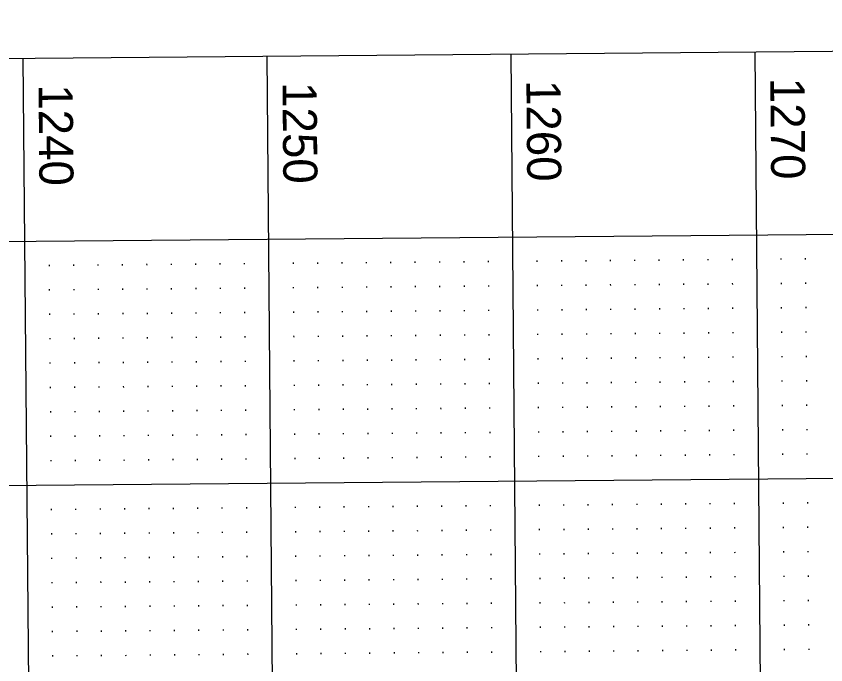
# Model space of a CAD drawing. Extents: x 2149873 to 2152007, y 140538 to 142349.
# Drawn here: x 2150024.4 to 2150190.3, y 142035.8 to 142168.7 of the extents above; entities that cross this region are included whole.
import ezdxf

# ---------------------------------------------------------------- set-up
doc = ezdxf.new("R2010")
doc.units = 0
for name, color, linetype in [('SHT_Plan_Profile_Sheet_Elev_Txt', 7, 'Continuous'), ('SHT_Profile_Grid_Major', 7, 'Continuous'), ('SHT_Profile_Grid_Minor', 7, 'Continuous'), ('SHT_Sheet_Border', 7, 'Continuous')]:
    doc.layers.add(name, color=color, linetype=linetype)

msp = doc.modelspace()

# ---------------------------------------------------------------- linework, layer by layer
at = {"layer": 'SHT_Profile_Grid_Major'}
for p, q in [((2150025.72, 142160.07), (2150039.51, 140585.13)), ((2150075.72, 142160.51), (2150089.51, 140585.57)), ((2150125.72, 142160.94), (2150139.51, 140586)), ((2150175.72, 142161.38), (2150189.5, 140586.44)), ((2149976.49, 142072.13), (2150476.47, 142076.51))]:
    msp.add_line(p, q, dxfattribs=at)
at = {"layer": 'SHT_Profile_Grid_Minor'}
for p, q in [((2150116.09, 142118.48), (2150116.09, 142118.23)), ((2150121.09, 142118.53), (2150121.09, 142118.28)), ((2150131.09, 142118.61), (2150131.09, 142118.36)), ((2150136.09, 142118.66), (2150136.09, 142118.41)), ((2150141.09, 142118.7), (2150141.09, 142118.45)), ((2150146.09, 142118.75), (2150146.09, 142118.5)), ((2150151.09, 142118.79), (2150151.09, 142118.54)), ((2150156.09, 142118.83), (2150156.09, 142118.58)), ((2150161.09, 142118.88), (2150161.09, 142118.63)), ((2150166.09, 142118.92), (2150166.09, 142118.67)), ((2150171.09, 142118.96), (2150171.09, 142118.71)), ((2150181.09, 142119.05), (2150181.09, 142118.8)), ((2150186.09, 142119.1), (2150186.09, 142118.85)), ((2150031.09, 142117.74), (2150031.1, 142117.49)), ((2150036.09, 142117.78), (2150036.1, 142117.53)), ((2150041.09, 142117.83), (2150041.1, 142117.58)), ((2150046.09, 142117.87), (2150046.1, 142117.62)), ((2150051.09, 142117.91), (2150051.1, 142117.66)), ((2150056.09, 142117.96), (2150056.1, 142117.71)), ((2150061.09, 142118), (2150061.1, 142117.75)), ((2150066.09, 142118.05), (2150066.1, 142117.8)), ((2150071.09, 142118.09), (2150071.1, 142117.84)), ((2150081.09, 142118.18), (2150081.1, 142117.93)), ((2150086.09, 142118.22), (2150086.09, 142117.97)), ((2150091.09, 142118.26), (2150091.09, 142118.01)), ((2150096.09, 142118.31), (2150096.09, 142118.06)), ((2150101.09, 142118.35), (2150101.09, 142118.1)), ((2150106.09, 142118.4), (2150106.09, 142118.15)), ((2150111.09, 142118.44), (2150111.09, 142118.19)), ((2150116.14, 142113.48), (2150116.14, 142113.23)), ((2150121.14, 142113.53), (2150121.14, 142113.28)), ((2150131.13, 142113.61), (2150131.14, 142113.36)), ((2150136.13, 142113.66), (2150136.14, 142113.41)), ((2150141.13, 142113.7), (2150141.14, 142113.45)), ((2150146.13, 142113.75), (2150146.14, 142113.5)), ((2150151.13, 142113.79), (2150151.14, 142113.54)), ((2150156.13, 142113.83), (2150156.14, 142113.58)), ((2150161.13, 142113.88), (2150161.14, 142113.63)), ((2150166.13, 142113.92), (2150166.14, 142113.67)), ((2150171.13, 142113.96), (2150171.14, 142113.71)), ((2150181.13, 142114.05), (2150181.14, 142113.8)), ((2150186.13, 142114.1), (2150186.13, 142113.85)), ((2150031.14, 142112.74), (2150031.14, 142112.49)), ((2150036.14, 142112.78), (2150036.14, 142112.53)), ((2150041.14, 142112.83), (2150041.14, 142112.58)), ((2150046.14, 142112.87), (2150046.14, 142112.62)), ((2150051.14, 142112.91), (2150051.14, 142112.66)), ((2150056.14, 142112.96), (2150056.14, 142112.71)), ((2150061.14, 142113), (2150061.14, 142112.75)), ((2150066.14, 142113.05), (2150066.14, 142112.8)), ((2150071.14, 142113.09), (2150071.14, 142112.84)), ((2150081.14, 142113.18), (2150081.14, 142112.93)), ((2150086.14, 142113.22), (2150086.14, 142112.97)), ((2150091.14, 142113.26), (2150091.14, 142113.01)), ((2150096.14, 142113.31), (2150096.14, 142113.06)), ((2150101.14, 142113.35), (2150101.14, 142113.1)), ((2150106.14, 142113.4), (2150106.14, 142113.15)), ((2150111.14, 142113.44), (2150111.14, 142113.19)), ((2150121.18, 142108.53), (2150121.18, 142108.28)), ((2150131.18, 142108.61), (2150131.18, 142108.36)), ((2150136.18, 142108.66), (2150136.18, 142108.41)), ((2150141.18, 142108.7), (2150141.18, 142108.45)), ((2150146.18, 142108.75), (2150146.18, 142108.5)), ((2150151.18, 142108.79), (2150151.18, 142108.54)), ((2150156.18, 142108.83), (2150156.18, 142108.58)), ((2150161.18, 142108.88), (2150161.18, 142108.63)), ((2150166.18, 142108.92), (2150166.18, 142108.67)), ((2150171.18, 142108.96), (2150171.18, 142108.71)), ((2150181.18, 142109.05), (2150181.18, 142108.8)), ((2150186.18, 142109.1), (2150186.18, 142108.85)), ((2150031.18, 142107.74), (2150031.18, 142107.49)), ((2150036.18, 142107.78), (2150036.18, 142107.53)), ((2150041.18, 142107.83), (2150041.18, 142107.58)), ((2150046.18, 142107.87), (2150046.18, 142107.62)), ((2150051.18, 142107.91), (2150051.18, 142107.66)), ((2150056.18, 142107.96), (2150056.18, 142107.71)), ((2150061.18, 142108), (2150061.18, 142107.75)), ((2150066.18, 142108.05), (2150066.18, 142107.8)), ((2150071.18, 142108.09), (2150071.18, 142107.84)), ((2150081.18, 142108.18), (2150081.18, 142107.93)), ((2150086.18, 142108.22), (2150086.18, 142107.97)), ((2150091.18, 142108.26), (2150091.18, 142108.01)), ((2150096.18, 142108.31), (2150096.18, 142108.06)), ((2150101.18, 142108.35), (2150101.18, 142108.1)), ((2150106.18, 142108.4), (2150106.18, 142108.15)), ((2150111.18, 142108.44), (2150111.18, 142108.19)), ((2150116.18, 142108.48), (2150116.18, 142108.23)), ((2150121.22, 142103.53), (2150121.22, 142103.28)), ((2150131.22, 142103.62), (2150131.22, 142103.37)), ((2150136.22, 142103.66), (2150136.22, 142103.41)), ((2150141.22, 142103.7), (2150141.22, 142103.45)), ((2150146.22, 142103.75), (2150146.22, 142103.5)), ((2150151.22, 142103.79), (2150151.22, 142103.54)), ((2150156.22, 142103.83), (2150156.22, 142103.58)), ((2150161.22, 142103.88), (2150161.22, 142103.63)), ((2150166.22, 142103.92), (2150166.22, 142103.67)), ((2150171.22, 142103.97), (2150171.22, 142103.72)), ((2150181.22, 142104.05), (2150181.22, 142103.8)), ((2150186.22, 142104.1), (2150186.22, 142103.85)), ((2150031.23, 142102.74), (2150031.23, 142102.49)), ((2150036.23, 142102.78), (2150036.23, 142102.53)), ((2150041.23, 142102.83), (2150041.23, 142102.58)), ((2150046.23, 142102.87), (2150046.23, 142102.62)), ((2150051.23, 142102.91), (2150051.23, 142102.66)), ((2150056.23, 142102.96), (2150056.23, 142102.71)), ((2150061.22, 142103), (2150061.23, 142102.75)), ((2150066.22, 142103.05), (2150066.23, 142102.8)), ((2150071.22, 142103.09), (2150071.23, 142102.84)), ((2150081.22, 142103.18), (2150081.23, 142102.93)), ((2150086.22, 142103.22), (2150086.23, 142102.97)), ((2150091.22, 142103.26), (2150091.23, 142103.01)), ((2150096.22, 142103.31), (2150096.23, 142103.06)), ((2150101.22, 142103.35), (2150101.23, 142103.1)), ((2150106.22, 142103.4), (2150106.23, 142103.15)), ((2150111.22, 142103.44), (2150111.23, 142103.19)), ((2150116.22, 142103.48), (2150116.22, 142103.23)), ((2150131.27, 142098.62), (2150131.27, 142098.37)), ((2150136.27, 142098.66), (2150136.27, 142098.41)), ((2150141.27, 142098.7), (2150141.27, 142098.45)), ((2150146.27, 142098.75), (2150146.27, 142098.5)), ((2150151.27, 142098.79), (2150151.27, 142098.54)), ((2150156.27, 142098.83), (2150156.27, 142098.58)), ((2150161.26, 142098.88), (2150161.27, 142098.63)), ((2150166.26, 142098.92), (2150166.27, 142098.67)), ((2150171.26, 142098.97), (2150171.27, 142098.72)), ((2150181.26, 142099.05), (2150181.27, 142098.8)), ((2150186.26, 142099.1), (2150186.27, 142098.85)), ((2150031.27, 142097.74), (2150031.27, 142097.49)), ((2150036.27, 142097.78), (2150036.27, 142097.53)), ((2150041.27, 142097.83), (2150041.27, 142097.58)), ((2150046.27, 142097.87), (2150046.27, 142097.62)), ((2150051.27, 142097.92), (2150051.27, 142097.67)), ((2150056.27, 142097.96), (2150056.27, 142097.71)), ((2150061.27, 142098), (2150061.27, 142097.75)), ((2150066.27, 142098.05), (2150066.27, 142097.8)), ((2150071.27, 142098.09), (2150071.27, 142097.84)), ((2150081.27, 142098.18), (2150081.27, 142097.93)), ((2150086.27, 142098.22), (2150086.27, 142097.97)), ((2150091.27, 142098.27), (2150091.27, 142098.02)), ((2150096.27, 142098.31), (2150096.27, 142098.06)), ((2150101.27, 142098.35), (2150101.27, 142098.1)), ((2150106.27, 142098.4), (2150106.27, 142098.15)), ((2150111.27, 142098.44), (2150111.27, 142098.19)), ((2150116.27, 142098.48), (2150116.27, 142098.23)), ((2150121.27, 142098.53), (2150121.27, 142098.28)), ((2150131.31, 142093.62), (2150131.31, 142093.37)), ((2150136.31, 142093.66), (2150136.31, 142093.41)), ((2150141.31, 142093.7), (2150141.31, 142093.45)), ((2150146.31, 142093.75), (2150146.31, 142093.5)), ((2150151.31, 142093.79), (2150151.31, 142093.54)), ((2150156.31, 142093.83), (2150156.31, 142093.58)), ((2150161.31, 142093.88), (2150161.31, 142093.63)), ((2150166.31, 142093.92), (2150166.31, 142093.67)), ((2150171.31, 142093.97), (2150171.31, 142093.72)), ((2150181.31, 142094.05), (2150181.31, 142093.8)), ((2150186.31, 142094.1), (2150186.31, 142093.85)), ((2150031.31, 142092.74), (2150031.32, 142092.49)), ((2150036.31, 142092.78), (2150036.32, 142092.53)), ((2150041.31, 142092.83), (2150041.32, 142092.58)), ((2150046.31, 142092.87), (2150046.32, 142092.62)), ((2150051.31, 142092.92), (2150051.32, 142092.67)), ((2150056.31, 142092.96), (2150056.31, 142092.71)), ((2150061.31, 142093), (2150061.31, 142092.75)), ((2150066.31, 142093.05), (2150066.31, 142092.8)), ((2150071.31, 142093.09), (2150071.31, 142092.84)), ((2150081.31, 142093.18), (2150081.31, 142092.93)), ((2150086.31, 142093.22), (2150086.31, 142092.97)), ((2150091.31, 142093.27), (2150091.31, 142093.02)), ((2150096.31, 142093.31), (2150096.31, 142093.06)), ((2150101.31, 142093.35), (2150101.31, 142093.1)), ((2150106.31, 142093.4), (2150106.31, 142093.15)), ((2150111.31, 142093.44), (2150111.31, 142093.19)), ((2150116.31, 142093.48), (2150116.31, 142093.23)), ((2150121.31, 142093.53), (2150121.31, 142093.28)), ((2150131.35, 142088.62), (2150131.36, 142088.37)), ((2150136.35, 142088.66), (2150136.36, 142088.41)), ((2150141.35, 142088.7), (2150141.36, 142088.45)), ((2150146.35, 142088.75), (2150146.36, 142088.5)), ((2150151.35, 142088.79), (2150151.35, 142088.54)), ((2150156.35, 142088.83), (2150156.35, 142088.58)), ((2150161.35, 142088.88), (2150161.35, 142088.63)), ((2150166.35, 142088.92), (2150166.35, 142088.67)), ((2150171.35, 142088.97), (2150171.35, 142088.72)), ((2150181.35, 142089.05), (2150181.35, 142088.8)), ((2150186.35, 142089.1), (2150186.35, 142088.85)), ((2150031.36, 142087.74), (2150031.36, 142087.49)), ((2150036.36, 142087.78), (2150036.36, 142087.53)), ((2150041.36, 142087.83), (2150041.36, 142087.58)), ((2150046.36, 142087.87), (2150046.36, 142087.62)), ((2150051.36, 142087.92), (2150051.36, 142087.67)), ((2150056.36, 142087.96), (2150056.36, 142087.71)), ((2150061.36, 142088), (2150061.36, 142087.75)), ((2150066.36, 142088.05), (2150066.36, 142087.8)), ((2150071.36, 142088.09), (2150071.36, 142087.84)), ((2150081.36, 142088.18), (2150081.36, 142087.93)), ((2150086.36, 142088.22), (2150086.36, 142087.97)), ((2150091.36, 142088.27), (2150091.36, 142088.02)), ((2150096.35, 142088.31), (2150096.36, 142088.06)), ((2150101.35, 142088.35), (2150101.36, 142088.1)), ((2150106.35, 142088.4), (2150106.36, 142088.15)), ((2150111.35, 142088.44), (2150111.36, 142088.19)), ((2150116.35, 142088.48), (2150116.36, 142088.23)), ((2150121.35, 142088.53), (2150121.36, 142088.28)), ((2150131.4, 142083.62), (2150131.4, 142083.37)), ((2150136.4, 142083.66), (2150136.4, 142083.41)), ((2150141.4, 142083.7), (2150141.4, 142083.45)), ((2150146.4, 142083.75), (2150146.4, 142083.5)), ((2150151.4, 142083.79), (2150151.4, 142083.54)), ((2150156.4, 142083.83), (2150156.4, 142083.58)), ((2150161.4, 142083.88), (2150161.4, 142083.63)), ((2150166.4, 142083.92), (2150166.4, 142083.67)), ((2150171.4, 142083.97), (2150171.4, 142083.72)), ((2150181.4, 142084.05), (2150181.4, 142083.8)), ((2150186.4, 142084.1), (2150186.4, 142083.85)), ((2150031.4, 142082.74), (2150031.4, 142082.49)), ((2150036.4, 142082.78), (2150036.4, 142082.53)), ((2150041.4, 142082.83), (2150041.4, 142082.58)), ((2150046.4, 142082.87), (2150046.4, 142082.62)), ((2150051.4, 142082.92), (2150051.4, 142082.67)), ((2150056.4, 142082.96), (2150056.4, 142082.71)), ((2150061.4, 142083), (2150061.4, 142082.75)), ((2150066.4, 142083.05), (2150066.4, 142082.8)), ((2150071.4, 142083.09), (2150071.4, 142082.84)), ((2150081.4, 142083.18), (2150081.4, 142082.93)), ((2150086.4, 142083.22), (2150086.4, 142082.97)), ((2150091.4, 142083.27), (2150091.4, 142083.02)), ((2150096.4, 142083.31), (2150096.4, 142083.06)), ((2150101.4, 142083.35), (2150101.4, 142083.1)), ((2150106.4, 142083.4), (2150106.4, 142083.15)), ((2150111.4, 142083.44), (2150111.4, 142083.19)), ((2150116.4, 142083.48), (2150116.4, 142083.23)), ((2150121.4, 142083.53), (2150121.4, 142083.28)), ((2150136.44, 142078.66), (2150136.44, 142078.41)), ((2150141.44, 142078.7), (2150141.44, 142078.45)), ((2150146.44, 142078.75), (2150146.44, 142078.5)), ((2150151.44, 142078.79), (2150151.44, 142078.54)), ((2150156.44, 142078.83), (2150156.44, 142078.58)), ((2150161.44, 142078.88), (2150161.44, 142078.63)), ((2150166.44, 142078.92), (2150166.44, 142078.67)), ((2150171.44, 142078.97), (2150171.44, 142078.72)), ((2150181.44, 142079.05), (2150181.44, 142078.8)), ((2150186.44, 142079.1), (2150186.44, 142078.85)), ((2150031.44, 142077.74), (2150031.45, 142077.49)), ((2150036.44, 142077.78), (2150036.45, 142077.53)), ((2150041.44, 142077.83), (2150041.45, 142077.58)), ((2150046.44, 142077.87), (2150046.45, 142077.62)), ((2150051.44, 142077.92), (2150051.45, 142077.67)), ((2150056.44, 142077.96), (2150056.45, 142077.71)), ((2150061.44, 142078), (2150061.45, 142077.75)), ((2150066.44, 142078.05), (2150066.45, 142077.8)), ((2150071.44, 142078.09), (2150071.45, 142077.84)), ((2150081.44, 142078.18), (2150081.45, 142077.93)), ((2150086.44, 142078.22), (2150086.44, 142077.97)), ((2150091.44, 142078.27), (2150091.44, 142078.02)), ((2150096.44, 142078.31), (2150096.44, 142078.06)), ((2150101.44, 142078.35), (2150101.44, 142078.1)), ((2150106.44, 142078.4), (2150106.44, 142078.15)), ((2150111.44, 142078.44), (2150111.44, 142078.19)), ((2150116.44, 142078.48), (2150116.44, 142078.23)), ((2150121.44, 142078.53), (2150121.44, 142078.28)), ((2150131.44, 142078.62), (2150131.44, 142078.37)), ((2150141.53, 142068.7), (2150141.53, 142068.45)), ((2150146.53, 142068.75), (2150146.53, 142068.5)), ((2150151.53, 142068.79), (2150151.53, 142068.54)), ((2150156.53, 142068.84), (2150156.53, 142068.59)), ((2150161.53, 142068.88), (2150161.53, 142068.63)), ((2150166.53, 142068.92), (2150166.53, 142068.67)), ((2150171.53, 142068.97), (2150171.53, 142068.72)), ((2150181.53, 142069.05), (2150181.53, 142068.8)), ((2150186.53, 142069.1), (2150186.53, 142068.85)), ((2150031.53, 142067.74), (2150031.53, 142067.49)), ((2150036.53, 142067.78), (2150036.53, 142067.53)), ((2150041.53, 142067.83), (2150041.53, 142067.58)), ((2150046.53, 142067.87), (2150046.53, 142067.62)), ((2150051.53, 142067.92), (2150051.53, 142067.67)), ((2150056.53, 142067.96), (2150056.53, 142067.71)), ((2150061.53, 142068), (2150061.53, 142067.75)), ((2150066.53, 142068.05), (2150066.53, 142067.8)), ((2150071.53, 142068.09), (2150071.53, 142067.84)), ((2150081.53, 142068.18), (2150081.53, 142067.93)), ((2150086.53, 142068.22), (2150086.53, 142067.97)), ((2150091.53, 142068.27), (2150091.53, 142068.02)), ((2150096.53, 142068.31), (2150096.53, 142068.06)), ((2150101.53, 142068.35), (2150101.53, 142068.1)), ((2150106.53, 142068.4), (2150106.53, 142068.15)), ((2150111.53, 142068.44), (2150111.53, 142068.19)), ((2150116.53, 142068.49), (2150116.53, 142068.24)), ((2150121.53, 142068.53), (2150121.53, 142068.28)), ((2150131.53, 142068.62), (2150131.53, 142068.37)), ((2150136.53, 142068.66), (2150136.53, 142068.41)), ((2150141.57, 142063.7), (2150141.57, 142063.45)), ((2150146.57, 142063.75), (2150146.57, 142063.5)), ((2150151.57, 142063.79), (2150151.57, 142063.54)), ((2150156.57, 142063.84), (2150156.57, 142063.59)), ((2150161.57, 142063.88), (2150161.57, 142063.63)), ((2150166.57, 142063.92), (2150166.57, 142063.67)), ((2150171.57, 142063.97), (2150171.57, 142063.72)), ((2150181.57, 142064.05), (2150181.57, 142063.8)), ((2150186.57, 142064.1), (2150186.57, 142063.85)), ((2150031.58, 142062.74), (2150031.58, 142062.49)), ((2150036.58, 142062.79), (2150036.58, 142062.54)), ((2150041.58, 142062.83), (2150041.58, 142062.58)), ((2150046.58, 142062.87), (2150046.58, 142062.62)), ((2150051.58, 142062.92), (2150051.58, 142062.67)), ((2150056.58, 142062.96), (2150056.58, 142062.71)), ((2150061.58, 142063), (2150061.58, 142062.75)), ((2150066.57, 142063.05), (2150066.58, 142062.8)), ((2150071.57, 142063.09), (2150071.58, 142062.84)), ((2150081.57, 142063.18), (2150081.58, 142062.93)), ((2150086.57, 142063.22), (2150086.58, 142062.97)), ((2150091.57, 142063.27), (2150091.58, 142063.02)), ((2150096.57, 142063.31), (2150096.58, 142063.06)), ((2150101.57, 142063.35), (2150101.58, 142063.1)), ((2150106.57, 142063.4), (2150106.58, 142063.15)), ((2150111.57, 142063.44), (2150111.58, 142063.19)), ((2150116.57, 142063.49), (2150116.58, 142063.24)), ((2150121.57, 142063.53), (2150121.57, 142063.28)), ((2150131.57, 142063.62), (2150131.57, 142063.37)), ((2150136.57, 142063.66), (2150136.57, 142063.41)), ((2150146.62, 142058.75), (2150146.62, 142058.5)), ((2150151.62, 142058.79), (2150151.62, 142058.54)), ((2150156.62, 142058.84), (2150156.62, 142058.59)), ((2150161.61, 142058.88), (2150161.62, 142058.63)), ((2150166.61, 142058.92), (2150166.62, 142058.67)), ((2150171.61, 142058.97), (2150171.62, 142058.72)), ((2150181.61, 142059.05), (2150181.62, 142058.8)), ((2150186.61, 142059.1), (2150186.62, 142058.85)), ((2150031.62, 142057.74), (2150031.62, 142057.49)), ((2150036.62, 142057.79), (2150036.62, 142057.54)), ((2150041.62, 142057.83), (2150041.62, 142057.58)), ((2150046.62, 142057.87), (2150046.62, 142057.62)), ((2150051.62, 142057.92), (2150051.62, 142057.67)), ((2150056.62, 142057.96), (2150056.62, 142057.71)), ((2150061.62, 142058), (2150061.62, 142057.75)), ((2150066.62, 142058.05), (2150066.62, 142057.8)), ((2150071.62, 142058.09), (2150071.62, 142057.84)), ((2150081.62, 142058.18), (2150081.62, 142057.93)), ((2150086.62, 142058.22), (2150086.62, 142057.97)), ((2150091.62, 142058.27), (2150091.62, 142058.02)), ((2150096.62, 142058.31), (2150096.62, 142058.06)), ((2150101.62, 142058.35), (2150101.62, 142058.1)), ((2150106.62, 142058.4), (2150106.62, 142058.15)), ((2150111.62, 142058.44), (2150111.62, 142058.19)), ((2150116.62, 142058.49), (2150116.62, 142058.24)), ((2150121.62, 142058.53), (2150121.62, 142058.28)), ((2150131.62, 142058.62), (2150131.62, 142058.37)), ((2150136.62, 142058.66), (2150136.62, 142058.41)), ((2150141.62, 142058.7), (2150141.62, 142058.45)), ((2150146.66, 142053.75), (2150146.66, 142053.5)), ((2150151.66, 142053.79), (2150151.66, 142053.54)), ((2150156.66, 142053.84), (2150156.66, 142053.59)), ((2150161.66, 142053.88), (2150161.66, 142053.63)), ((2150166.66, 142053.92), (2150166.66, 142053.67)), ((2150171.66, 142053.97), (2150171.66, 142053.72)), ((2150181.66, 142054.05), (2150181.66, 142053.8)), ((2150186.66, 142054.1), (2150186.66, 142053.85)), ((2150031.66, 142052.74), (2150031.67, 142052.49)), ((2150036.66, 142052.79), (2150036.67, 142052.54)), ((2150041.66, 142052.83), (2150041.67, 142052.58)), ((2150046.66, 142052.87), (2150046.67, 142052.62)), ((2150051.66, 142052.92), (2150051.67, 142052.67)), ((2150056.66, 142052.96), (2150056.66, 142052.71)), ((2150061.66, 142053), (2150061.66, 142052.75)), ((2150066.66, 142053.05), (2150066.66, 142052.8)), ((2150071.66, 142053.09), (2150071.66, 142052.84)), ((2150081.66, 142053.18), (2150081.66, 142052.93)), ((2150086.66, 142053.22), (2150086.66, 142052.97)), ((2150091.66, 142053.27), (2150091.66, 142053.02)), ((2150096.66, 142053.31), (2150096.66, 142053.06)), ((2150101.66, 142053.35), (2150101.66, 142053.1)), ((2150106.66, 142053.4), (2150106.66, 142053.15)), ((2150111.66, 142053.44), (2150111.66, 142053.19)), ((2150116.66, 142053.49), (2150116.66, 142053.24)), ((2150121.66, 142053.53), (2150121.66, 142053.28)), ((2150131.66, 142053.62), (2150131.66, 142053.37)), ((2150136.66, 142053.66), (2150136.66, 142053.41)), ((2150141.66, 142053.7), (2150141.66, 142053.45)), ((2150151.7, 142048.79), (2150151.71, 142048.54)), ((2150156.7, 142048.84), (2150156.7, 142048.59)), ((2150161.7, 142048.88), (2150161.7, 142048.63)), ((2150166.7, 142048.92), (2150166.7, 142048.67)), ((2150171.7, 142048.97), (2150171.7, 142048.72)), ((2150181.7, 142049.05), (2150181.7, 142048.8)), ((2150186.7, 142049.1), (2150186.7, 142048.85)), ((2150031.71, 142047.74), (2150031.71, 142047.49)), ((2150036.71, 142047.79), (2150036.71, 142047.54)), ((2150041.71, 142047.83), (2150041.71, 142047.58)), ((2150046.71, 142047.87), (2150046.71, 142047.62)), ((2150051.71, 142047.92), (2150051.71, 142047.67)), ((2150056.71, 142047.96), (2150056.71, 142047.71)), ((2150061.71, 142048), (2150061.71, 142047.75)), ((2150066.71, 142048.05), (2150066.71, 142047.8)), ((2150071.71, 142048.09), (2150071.71, 142047.84)), ((2150081.71, 142048.18), (2150081.71, 142047.93)), ((2150086.71, 142048.22), (2150086.71, 142047.97)), ((2150091.71, 142048.27), (2150091.71, 142048.02)), ((2150096.7, 142048.31), (2150096.71, 142048.06)), ((2150101.7, 142048.35), (2150101.71, 142048.1)), ((2150106.7, 142048.4), (2150106.71, 142048.15)), ((2150111.7, 142048.44), (2150111.71, 142048.19)), ((2150116.7, 142048.49), (2150116.71, 142048.24)), ((2150121.7, 142048.53), (2150121.71, 142048.28)), ((2150131.7, 142048.62), (2150131.71, 142048.37)), ((2150136.7, 142048.66), (2150136.71, 142048.41)), ((2150141.7, 142048.7), (2150141.71, 142048.45)), ((2150146.7, 142048.75), (2150146.71, 142048.5)), ((2150151.75, 142043.79), (2150151.75, 142043.54)), ((2150156.75, 142043.84), (2150156.75, 142043.59)), ((2150161.75, 142043.88), (2150161.75, 142043.63)), ((2150166.75, 142043.92), (2150166.75, 142043.67)), ((2150171.75, 142043.97), (2150171.75, 142043.72)), ((2150181.75, 142044.06), (2150181.75, 142043.81)), ((2150186.75, 142044.1), (2150186.75, 142043.85)), ((2150031.75, 142042.74), (2150031.75, 142042.49)), ((2150036.75, 142042.79), (2150036.75, 142042.54)), ((2150041.75, 142042.83), (2150041.75, 142042.58)), ((2150046.75, 142042.87), (2150046.75, 142042.62)), ((2150051.75, 142042.92), (2150051.75, 142042.67)), ((2150056.75, 142042.96), (2150056.75, 142042.71)), ((2150061.75, 142043), (2150061.75, 142042.75)), ((2150066.75, 142043.05), (2150066.75, 142042.8)), ((2150071.75, 142043.09), (2150071.75, 142042.84)), ((2150081.75, 142043.18), (2150081.75, 142042.93)), ((2150086.75, 142043.22), (2150086.75, 142042.97)), ((2150091.75, 142043.27), (2150091.75, 142043.02)), ((2150096.75, 142043.31), (2150096.75, 142043.06)), ((2150101.75, 142043.35), (2150101.75, 142043.1)), ((2150106.75, 142043.4), (2150106.75, 142043.15)), ((2150111.75, 142043.44), (2150111.75, 142043.19)), ((2150116.75, 142043.49), (2150116.75, 142043.24)), ((2150121.75, 142043.53), (2150121.75, 142043.28)), ((2150131.75, 142043.62), (2150131.75, 142043.37)), ((2150136.75, 142043.66), (2150136.75, 142043.41)), ((2150141.75, 142043.7), (2150141.75, 142043.45)), ((2150146.75, 142043.75), (2150146.75, 142043.5)), ((2150156.79, 142038.84), (2150156.79, 142038.59)), ((2150161.79, 142038.88), (2150161.79, 142038.63)), ((2150166.79, 142038.92), (2150166.79, 142038.67)), ((2150171.79, 142038.97), (2150171.79, 142038.72)), ((2150181.79, 142039.06), (2150181.79, 142038.81)), ((2150186.79, 142039.1), (2150186.79, 142038.85)), ((2150031.8, 142037.74), (2150031.8, 142037.49)), ((2150036.79, 142037.79), (2150036.8, 142037.54)), ((2150041.79, 142037.83), (2150041.8, 142037.58)), ((2150046.79, 142037.87), (2150046.8, 142037.62)), ((2150051.79, 142037.92), (2150051.8, 142037.67)), ((2150056.79, 142037.96), (2150056.8, 142037.71)), ((2150061.79, 142038), (2150061.8, 142037.75)), ((2150066.79, 142038.05), (2150066.8, 142037.8)), ((2150071.79, 142038.09), (2150071.8, 142037.84)), ((2150081.79, 142038.18), (2150081.8, 142037.93)), ((2150086.79, 142038.22), (2150086.8, 142037.97)), ((2150091.79, 142038.27), (2150091.79, 142038.02)), ((2150096.79, 142038.31), (2150096.79, 142038.06)), ((2150101.79, 142038.35), (2150101.79, 142038.1)), ((2150106.79, 142038.4), (2150106.79, 142038.15)), ((2150111.79, 142038.44), (2150111.79, 142038.19)), ((2150116.79, 142038.49), (2150116.79, 142038.24)), ((2150121.79, 142038.53), (2150121.79, 142038.28)), ((2150131.79, 142038.62), (2150131.79, 142038.37)), ((2150136.79, 142038.66), (2150136.79, 142038.41)), ((2150141.79, 142038.71), (2150141.79, 142038.46)), ((2150146.79, 142038.75), (2150146.79, 142038.5)), ((2150151.79, 142038.79), (2150151.79, 142038.54))]:
    msp.add_line(p, q, dxfattribs=at)
at = {"layer": 'SHT_Sheet_Border'}
msp.add_line((2149976.05, 142122.13), (2150476.04, 142126.51), dxfattribs=at)
msp.add_lwpolyline([(2151008.19, 142168.67), (2151021.97, 140593.73), (2149972.01, 140584.54), (2149958.23, 142159.48)], close=True, dxfattribs=at)

# ---------------------------------------------------------------- texts
at = {"layer": 'SHT_Plan_Profile_Sheet_Elev_Txt'}
for s, p in [('1270', (2150178.92, 142156.01)), ('1240', (2150028.93, 142154.7)), ('1250', (2150078.93, 142155.14)), ('1260', (2150128.92, 142155.58))]:
    msp.add_text(s, height=7, rotation=270.5015, dxfattribs=at).set_placement(p)

doc.saveas('drawing.dxf')
